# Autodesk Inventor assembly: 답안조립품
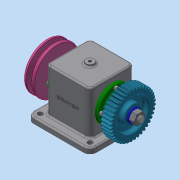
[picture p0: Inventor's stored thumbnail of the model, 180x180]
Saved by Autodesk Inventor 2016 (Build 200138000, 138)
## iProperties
Created: 2022-07
Part Number: 답안조립품
Material: 일반
Document SubType Name: Assembly
Designer: PC-1-6
Author: PC-1-6
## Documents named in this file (12)
- C:\Users\PC-1-6\Desktop\720706V1010\답안조립품.iam
- C:\Users\PC-1-6\Desktop\720706V1010\본체.ipt
- C:\Users\PC-1-6\Desktop\720706V1010\베어링 6204.ipt
- C:\Users\PC-1-6\Desktop\720706V1010\커버.ipt
- C:\Users\PC-1-6\Desktop\720706V1010\축.ipt
- C:\Users\PC-1-6\Desktop\720706V1010\오일실 20x35x8.ipt
- C:\Users\PC-1-6\Desktop\720706V1010\볼트 M4x0.7.ipt
- C:\Users\PC-1-6\Desktop\720706V1010\키 5x5.ipt
- C:\Users\PC-1-6\Desktop\720706V1010\V벨트풀리.ipt
- C:\Users\PC-1-6\Desktop\720706V1010\스퍼기어.ipt
- C:\Users\PC-1-6\Desktop\720706V1010\와셔 12x24.ipt
- C:\Users\PC-1-6\Desktop\720706V1010\너트 M12x1.25.ipt
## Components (1 placed, 1 different names)
1. V벨트풀리:1
